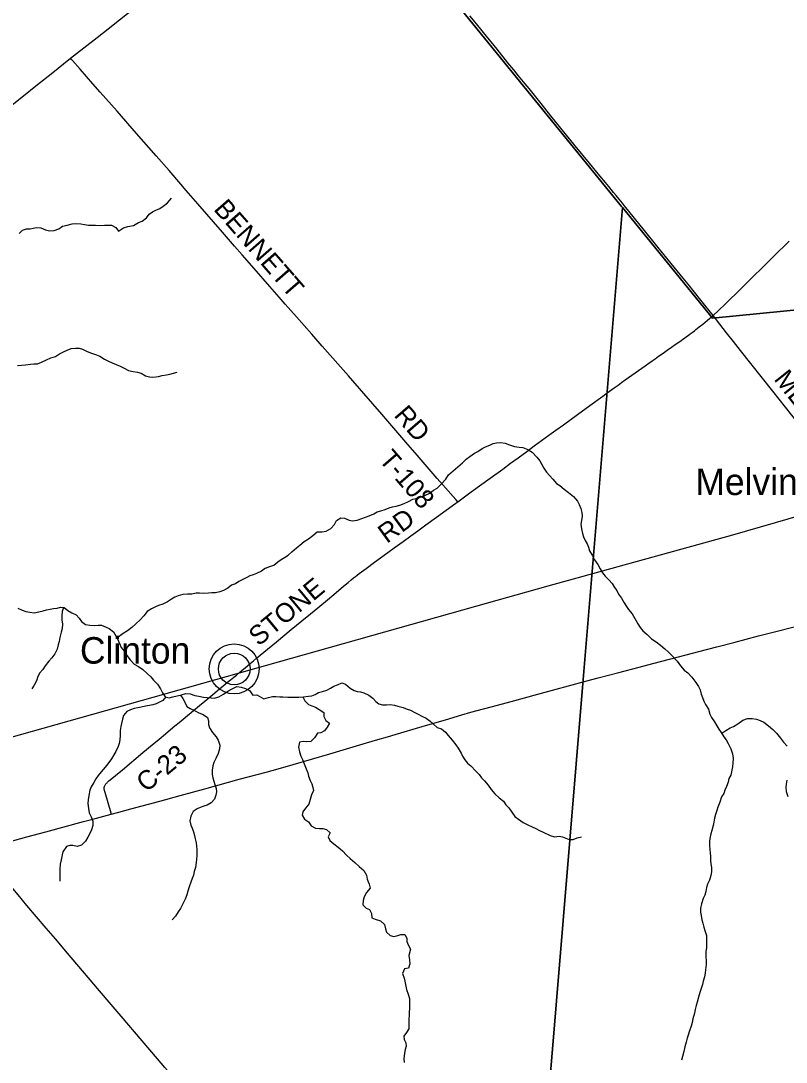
# Model space of a CAD drawing. Extents: x 1442749 to 1756758, y 235267 to 677782.
# Drawn here: x 1611789 to 1623834, y 530141 to 546534 of the extents above; entities that cross this region are included whole.
import ezdxf

# ---------------------------------------------------------------- set-up
doc = ezdxf.new("R2010")
doc.units = 0
for name, color, linetype in [('GM_X_County_Road', 7, 'Continuous'), ('GM_X_County_Road_Text', 7, 'Continuous'), ('GM_X_Major_River', 7, 'Continuous'), ('GM_X_Minor_River', 7, 'Continuous'), ('GM_X_Rail_Line', 7, 'Continuous'), ('GM_X_Township', 7, 'Continuous'), ('GM_X_Township_Road', 7, 'Continuous'), ('GM_X_Township_Road_Text', 7, 'Continuous'), ('GM_X_Unincorporated', 7, 'Continuous'), ('GM_X_Unincorporated_Location', 7, 'Continuous'), ('GM_X_Unincorporated_Text', 7, 'Continuous'), ('GM_X_US_Route', 7, 'Continuous')]:
    doc.layers.add(name, color=color, linetype=linetype)

msp = doc.modelspace()

# ---------------------------------------------------------------- linework, layer by layer
at = {"layer": 'GM_X_County_Road'}
for points in [[(1612571, 545944), (1612619, 545982), (1612991, 546273), (1613163, 546410), (1613344, 546552), (1613593, 546749), (1613910, 546999), (1613982, 547057), (1614013, 547086), (1614034, 547110), (1614082, 547170), (1614090, 547182)], [(1621256, 543663), (1621205, 543726), (1621157, 543784), (1621117, 543833), (1621079, 543879), (1621043, 543924), (1620991, 543987), (1620900, 544096), (1620740, 544292), (1620514, 544569), (1620132, 545041), (1619976, 545233), (1619788, 545467), (1619725, 545545), (1619623, 545670), (1619546, 545764), (1619456, 545875), (1619284, 546086), (1619072, 546348), (1618939, 546512), (1618857, 546612)], [(1611554, 545133), (1611806, 545334), (1612054, 545532), (1612265, 545699), (1612571, 545944)], [(1622686, 541893), (1622493, 542135), (1622290, 542389), (1622214, 542483), (1622025, 542715), (1621822, 542965), (1621603, 543235), (1621288, 543623), (1621256, 543663)], [(1622686, 541893), (1622770, 541973), (1622881, 542081), (1623120, 542315), (1623298, 542494), (1623470, 542662), (1623731, 542920), (1623785, 542973), (1623880, 543067)], [(1620998, 540662), (1621052, 540702), (1621126, 540755), (1621188, 540799), (1621244, 540839), (1621302, 540881), (1621613, 541103), (1621673, 541146), (1621724, 541182), (1621770, 541215), (1621824, 541253), (1621896, 541304), (1621960, 541349), (1622029, 541397), (1622088, 541437), (1622144, 541476), (1622179, 541500), (1622208, 541521), (1622236, 541541), (1622267, 541563), (1622293, 541582), (1622323, 541605), (1622355, 541629), (1622389, 541655), (1622414, 541676), (1622464, 541715), (1622520, 541761), (1622597, 541822), (1622686, 541893)], [(1622720, 541850), (1622686, 541893)], [(1624525, 539575), (1624463, 539652), (1624024, 540199), (1623623, 540706), (1623117, 541343), (1623003, 541487), (1622897, 541623), (1622789, 541761), (1622720, 541850)], [(1618665, 538964), (1618876, 539118), (1619176, 539336), (1619373, 539479), (1619497, 539571), (1619614, 539656), (1619750, 539755), (1619869, 539842), (1619985, 539927), (1620100, 540011), (1620211, 540091), (1620329, 540177), (1620550, 540337), (1620744, 540478), (1620951, 540628), (1620998, 540662)], [(1613213, 534046), (1613209, 534061), (1613114, 534384), (1613110, 534401), (1613107, 534414), (1613104, 534425), (1613103, 534434), (1613102, 534443), (1613101, 534450), (1613102, 534460), (1613103, 534469), (1613105, 534478), (1613107, 534485), (1613111, 534494), (1613115, 534503), (1613121, 534512), (1613127, 534521), (1613133, 534528), (1613139, 534535), (1613146, 534541), (1613154, 534549), (1613164, 534558), (1613176, 534568), (1613197, 534585), (1613390, 534745), (1613711, 535014), (1613858, 535136), (1613964, 535225), (1614065, 535310), (1614144, 535376), (1614214, 535434), (1614280, 535489), (1614343, 535541), (1614410, 535597), (1614470, 535648), (1614513, 535684), (1614565, 535727), (1614608, 535763), (1614652, 535799), (1614812, 535931), (1614917, 536018), (1614974, 536065), (1615043, 536122), (1615091, 536162), (1615141, 536202), (1615183, 536236), (1615230, 536275), (1615275, 536312), (1615318, 536348), (1615399, 536417), (1615449, 536458), (1615500, 536500), (1615614, 536594), (1615811, 536757), (1616046, 536951), (1616211, 537087), (1616348, 537201), (1616461, 537295), (1616614, 537421), (1616715, 537506), (1616831, 537601), (1616895, 537654), (1616943, 537694), (1616990, 537733), (1617026, 537764), (1617056, 537788), (1617082, 537809), (1617115, 537834), (1617150, 537860), (1617185, 537886), (1617224, 537914), (1617357, 538010), (1617565, 538163), (1617667, 538237), (1617808, 538339), (1617927, 538426), (1618036, 538506), (1618164, 538600), (1618329, 538720), (1618633, 538940), (1618665, 538964)], [(1616062, 527722), (1615880, 527924), (1615778, 528043), (1615654, 528187), (1615414, 528470), (1615095, 528841), (1614595, 529431), (1614445, 529605), (1614213, 529877), (1614058, 530056), (1613941, 530193), (1613701, 530475), (1613366, 530867), (1613181, 531084), (1612938, 531369), (1612522, 531859), (1612333, 532081), (1612189, 532251), (1611886, 532610), (1611745, 532778), (1611531, 533031), (1611414, 533169), (1611334, 533264), (1611146, 533486)]]:
    msp.add_lwpolyline(points, dxfattribs=at)
at = {"layer": 'GM_X_Major_River'}
msp.add_lwpolyline([(1611741, 537288), (1611808, 537256), (1611867, 537237), (1611933, 537223), (1611997, 537214), (1612070, 537232), (1612140, 537245), (1612192, 537262), (1612251, 537275), (1612305, 537282), (1612363, 537286), (1612416, 537303), (1612472, 537300), (1612531, 537253), (1612590, 537217), (1612658, 537182), (1612705, 537131), (1612746, 537080), (1612807, 537032), (1612875, 537019), (1612947, 537017), (1613007, 537022), (1613061, 537021), (1613130, 536987), (1613182, 536966), (1613247, 536915), (1613315, 536793)], dxfattribs=at)
at = {"layer": 'GM_X_Minor_River'}
for points in [[(1611765, 543188), (1611815, 543240), (1611878, 543261), (1611934, 543261), (1611984, 543270), (1612036, 543280), (1612106, 543275), (1612178, 543246), (1612238, 543229), (1612314, 543234), (1612385, 543262), (1612447, 543301), (1612516, 543320), (1612596, 543337), (1612654, 543345), (1612734, 543338), (1612790, 543327), (1612854, 543318), (1612913, 543318), (1612965, 543315), (1613039, 543314), (1613107, 543315), (1613159, 543317), (1613217, 543316), (1613283, 543279), (1613326, 543223), (1613407, 543276), (1613472, 543299), (1613564, 543310), (1613641, 543361), (1613699, 543381), (1613766, 543432), (1613807, 543492), (1613859, 543529), (1613916, 543555), (1613976, 543582), (1614029, 543618), (1614099, 543671), (1614158, 543741)], [(1611738, 541109), (1611798, 541114), (1611864, 541117), (1611941, 541127), (1611995, 541134), (1612053, 541137), (1612117, 541161), (1612192, 541200), (1612264, 541227), (1612335, 541252), (1612397, 541292), (1612462, 541325), (1612518, 541349), (1612579, 541378), (1612651, 541381), (1612707, 541381), (1612759, 541368), (1612831, 541331), (1612903, 541302), (1612978, 541275), (1613030, 541257), (1613108, 541206), (1613170, 541175), (1613226, 541150)], [(1613226, 541150), (1613291, 541125), (1613355, 541100), (1613413, 541068), (1613483, 541029), (1613555, 541012), (1613623, 541005), (1613683, 540988), (1613752, 540947), (1613812, 540931), (1613868, 540924), (1613955, 540933), (1614013, 540950), (1614081, 540964), (1614135, 540971), (1614194, 540990), (1614248, 541006)], [(1615641, 537919), (1615706, 537942), (1615771, 537963), (1615834, 538017), (1615884, 538054), (1615941, 538088), (1615994, 538125), (1616055, 538177), (1616126, 538238), (1616180, 538282), (1616249, 538337), (1616316, 538382), (1616383, 538434), (1616454, 538491), (1616529, 538492), (1616597, 538500), (1616666, 538543), (1616727, 538604), (1616758, 538670), (1616826, 538712), (1616883, 538705), (1616957, 538676), (1617011, 538663), (1617085, 538673), (1617154, 538702), (1617214, 538723), (1617271, 538741), (1617343, 538772), (1617396, 538805), (1617453, 538823), (1617523, 538840), (1617586, 538869), (1617636, 538885), (1617696, 538894), (1617753, 538908), (1617822, 538935), (1617890, 538966), (1617957, 539002), (1618031, 539019), (1618098, 539046), (1618148, 539062), (1618225, 539101), (1618284, 539146), (1618339, 539178), (1618402, 539239), (1618477, 539317), (1618520, 539386), (1618595, 539452), (1618666, 539515), (1618739, 539577), (1618800, 539632), (1618853, 539674), (1618930, 539727), (1618980, 539754), (1619051, 539802), (1619102, 539827), (1619169, 539855), (1619223, 539880), (1619277, 539891), (1619346, 539897), (1619410, 539886), (1619478, 539857), (1619558, 539832), (1619632, 539823), (1619688, 539815), (1619766, 539784), (1619836, 539745), (1619909, 539666), (1619955, 539609), (1619988, 539548), (1620020, 539490), (1620061, 539431), (1620113, 539373), (1620160, 539318), (1620222, 539251), (1620274, 539218), (1620339, 539161), (1620407, 539111), (1620489, 539045), (1620548, 538975), (1620575, 538918), (1620603, 538856), (1620618, 538793), (1620623, 538737), (1620615, 538669), (1620602, 538609), (1620613, 538535), (1620630, 538462), (1620644, 538410), (1620673, 538355), (1620703, 538301), (1620722, 538247), (1620739, 538190), (1620779, 538122), (1620816, 538051), (1620869, 537974), (1620909, 537907), (1620946, 537845), (1620984, 537794), (1621043, 537735), (1621093, 537679)], [(1615641, 537919), (1615576, 537869), (1615500, 537832), (1615445, 537813), (1615395, 537795), (1615344, 537772), (1615273, 537734), (1615221, 537709), (1615166, 537671), (1615106, 537648), (1615049, 537604), (1614978, 537565), (1614922, 537548), (1614853, 537532), (1614797, 537529), (1614743, 537526), (1614670, 537520), (1614602, 537523), (1614550, 537522), (1614479, 537511), (1614411, 537507), (1614341, 537504), (1614264, 537485), (1614213, 537461), (1614161, 537428), (1614098, 537388), (1614023, 537353), (1613955, 537330), (1613900, 537306), (1613844, 537279), (1613779, 537236), (1613726, 537170), (1613665, 537106), (1613600, 537041), (1613535, 536982), (1613470, 536930), (1613399, 536891), (1613302, 536815)], [(1621093, 537679), (1621132, 537616), (1621168, 537564), (1621195, 537511), (1621241, 537444), (1621282, 537374), (1621319, 537315), (1621351, 537265), (1621408, 537198), (1621450, 537123), (1621499, 537042), (1621538, 536982), (1621578, 536931), (1621648, 536876), (1621717, 536805), (1621787, 536758), (1621854, 536707), (1621922, 536648), (1621984, 536596), (1622047, 536531), (1622119, 536454), (1622170, 536379), (1622231, 536314), (1622287, 536269), (1622347, 536204), (1622414, 536119), (1622455, 536055), (1622479, 536004), (1622498, 535934), (1622515, 535880), (1622537, 535825), (1622564, 535773), (1622610, 535698), (1622635, 535618), (1622658, 535567), (1622704, 535500), (1622743, 535438), (1622775, 535383), (1622812, 535333), (1622853, 535264), (1622891, 535213), (1622922, 535157), (1622962, 535074), (1622987, 534996), (1623000, 534921), (1622993, 534855), (1622990, 534791), (1622980, 534739), (1622961, 534659), (1622934, 534607), (1622921, 534551), (1622896, 534483), (1622869, 534423), (1622851, 534371), (1622818, 534316), (1622791, 534236), (1622758, 534154), (1622741, 534102), (1622722, 534038), (1622705, 533980), (1622697, 533920), (1622684, 533868), (1622663, 533790), (1622650, 533738), (1622633, 533664), (1622627, 533614), (1622628, 533546), (1622631, 533493), (1622636, 533433), (1622642, 533383), (1622645, 533313), (1622650, 533261), (1622660, 533206), (1622661, 533138), (1622648, 533080), (1622625, 533008), (1622598, 532946), (1622582, 532890), (1622571, 532828), (1622552, 532772), (1622527, 532720), (1622500, 532636), (1622485, 532560), (1622485, 532504), (1622494, 532448), (1622505, 532384), (1622523, 532329), (1622538, 532267), (1622553, 532213), (1622579, 532134), (1622578, 532078), (1622581, 532018), (1622580, 531943), (1622568, 531881), (1622569, 531809), (1622576, 531727), (1622575, 531677), (1622566, 531595), (1622561, 531544), (1622549, 531484), (1622528, 531418)], [(1612459, 537301), (1612441, 537236), (1612433, 537170), (1612436, 537104), (1612443, 537035), (1612438, 536967), (1612422, 536913), (1612402, 536827), (1612390, 536763), (1612379, 536713), (1612362, 536645), (1612325, 536570), (1612276, 536506), (1612232, 536454), (1612171, 536379), (1612134, 536323), (1612089, 536271), (1612058, 536210), (1612034, 536142), (1612001, 536078), (1611960, 536016)], [(1613315, 536793), (1613367, 536670), (1613422, 536605), (1613459, 536542), (1613509, 536474), (1613574, 536409), (1613640, 536368), (1613707, 536325), (1613775, 536262), (1613836, 536205), (1613878, 536153), (1613941, 536092), (1613986, 536021), (1614018, 535954), (1614063, 535892), (1614123, 535877), (1614179, 535890), (1614251, 535906), (1614320, 535925), (1614384, 535946), (1614452, 535939), (1614526, 535913), (1614590, 535902), (1614666, 535887), (1614724, 535880), (1614784, 535875), (1614836, 535873), (1614907, 535894), (1614977, 535935), (1615048, 535981), (1615117, 536020), (1615191, 536053), (1615255, 536045), (1615325, 536022), (1615387, 535993), (1615438, 535920), (1615506, 535923), (1615613, 535863)], [(1615613, 535863), (1615685, 535882), (1615752, 535898), (1615802, 535897), (1615864, 535890), (1615914, 535890), (1615993, 535887), (1616059, 535888), (1616166, 535887), (1616240, 535890), (1616316, 535903), (1616369, 535909), (1616421, 535928), (1616472, 535962), (1616536, 535977), (1616607, 535998), (1616665, 536030), (1616716, 536061), (1616775, 536083), (1616843, 536114), (1616897, 536093), (1616973, 536030), (1617033, 535993), (1617085, 535975), (1617137, 535970), (1617187, 535956), (1617267, 535917), (1617330, 535872), (1617374, 535821), (1617426, 535782), (1617482, 535764), (1617544, 535767), (1617600, 535770), (1617669, 535760), (1617723, 535745), (1617805, 535722), (1617869, 535699), (1617923, 535681), (1617989, 535648), (1618045, 535617), (1618102, 535590), (1618166, 535556), (1618232, 535511), (1618284, 535460), (1618343, 535409), (1618411, 535388), (1618471, 535335), (1618513, 535285), (1618578, 535210), (1618637, 535135), (1618671, 535084), (1618718, 535008), (1618742, 534957), (1618777, 534899), (1618819, 534848), (1618870, 534807), (1618950, 534724), (1619003, 534670), (1619041, 534619), (1619084, 534568), (1619146, 534503), (1619189, 534435), (1619251, 534366), (1619316, 534301), (1619388, 534250), (1619421, 534193), (1619469, 534143), (1619514, 534078), (1619566, 534011), (1619624, 533969), (1619695, 533916), (1619769, 533875), (1619835, 533848), (1619895, 533819), (1619953, 533790), (1620011, 533764), (1620119, 533710), (1620187, 533691), (1620259, 533697), (1620313, 533686), (1620365, 533665), (1620417, 533647), (1620480, 533644), (1620544, 533671), (1620611, 533689)], [(1614304, 535920), (1614337, 535865), (1614371, 535810), (1614404, 535739), (1614456, 535711), (1614535, 535672), (1614589, 535643), (1614659, 535614), (1614726, 535565), (1614742, 535513), (1614745, 535459), (1614759, 535404), (1614808, 535332), (1614863, 535263), (1614893, 535208), (1614922, 535134), (1614917, 535074), (1614896, 535002), (1614865, 534934), (1614826, 534860), (1614810, 534806), (1614799, 534740), (1614802, 534670), (1614809, 534618), (1614825, 534563), (1614842, 534513), (1614861, 534451), (1614869, 534396), (1614860, 534344), (1614837, 534280), (1614787, 534223), (1614722, 534185), (1614668, 534170), (1614613, 534149), (1614563, 534127), (1614502, 534088), (1614465, 534016), (1614451, 533942), (1614466, 533873), (1614485, 533823), (1614507, 533769), (1614522, 533708), (1614535, 533658), (1614547, 533594), (1614554, 533542), (1614557, 533489), (1614561, 533439), (1614560, 533387), (1614556, 533335), (1614549, 533283), (1614536, 533207), (1614519, 533141), (1614507, 533087), (1614486, 533033), (1614465, 532977), (1614436, 532901), (1614417, 532831), (1614401, 532773), (1614376, 532705), (1614341, 532633), (1614300, 532562), (1614263, 532510), (1614224, 532440), (1614173, 532381)], [(1614071, 535890), (1614026, 535836), (1613974, 535809), (1613919, 535781), (1613865, 535768), (1613813, 535756), (1613750, 535743), (1613684, 535730), (1613628, 535720), (1613572, 535707), (1613513, 535689), (1613459, 535662), (1613406, 535596), (1613389, 535540), (1613372, 535474), (1613362, 535424), (1613353, 535360), (1613354, 535282), (1613349, 535214), (1613337, 535160), (1613320, 535108), (1613287, 535034), (1613254, 534980), (1613216, 534917), (1613158, 534837), (1613116, 534783), (1613053, 534710), (1613008, 534656), (1612969, 534599), (1612936, 534543), (1612896, 534475), (1612877, 534423), (1612862, 534337), (1612851, 534269), (1612846, 534213), (1612855, 534135), (1612867, 534066), (1612894, 534002), (1612921, 533935), (1612924, 533869), (1612904, 533797), (1612877, 533739), (1612844, 533685), (1612805, 533618), (1612742, 533556), (1612674, 533537), (1612610, 533554), (1612560, 533554), (1612510, 533535), (1612449, 533455), (1612442, 533403), (1612423, 533325), (1612406, 533257), (1612405, 533183), (1612403, 533123), (1612401, 532991)], [(1616227, 535890), (1616257, 535832), (1616319, 535773), (1616371, 535752), (1616425, 535730), (1616485, 535693), (1616556, 535646), (1616558, 535584), (1616591, 535521), (1616649, 535480), (1616608, 535417), (1616569, 535355), (1616512, 535327), (1616458, 535322), (1616413, 535248), (1616354, 535187), (1616286, 535186), (1616231, 535190), (1616173, 535177), (1616158, 535099), (1616175, 535026), (1616198, 534956), (1616222, 534905), (1616249, 534839), (1616282, 534760), (1616306, 534696), (1616317, 534644), (1616345, 534575), (1616368, 534525), (1616385, 534466), (1616393, 534416), (1616366, 534352), (1616343, 534274), (1616320, 534204), (1616271, 534139), (1616228, 534083), (1616219, 534029), (1616255, 533968), (1616317, 533926), (1616358, 533861), (1616428, 533826), (1616488, 533819), (1616544, 533819), (1616598, 533804), (1616658, 533749), (1616625, 533687), (1616651, 533633), (1616714, 533576), (1616782, 533525), (1616849, 533468), (1616913, 533399), (1616973, 533345), (1617046, 533282), (1617112, 533223), (1617185, 533156), (1617227, 533085), (1617240, 533023), (1617269, 532946), (1617288, 532882), (1617231, 532814), (1617194, 532742), (1617177, 532684), (1617173, 532618), (1617222, 532565), (1617274, 532543), (1617308, 532484), (1617315, 532414), (1617367, 532393), (1617449, 532366), (1617510, 532311), (1617528, 532239), (1617545, 532189), (1617603, 532136), (1617659, 532119), (1617721, 532133), (1617772, 532152), (1617834, 532149), (1617865, 532095), (1617865, 532043), (1617886, 531990), (1617920, 531922), (1617898, 531822), (1617905, 531751), (1617911, 531687), (1617888, 531623), (1617827, 531608), (1617794, 531536), (1617822, 531465), (1617833, 531415), (1617846, 531337), (1617858, 531287), (1617887, 531210), (1617906, 531144), (1617904, 530983), (1617902, 530933), (1617901, 530875), (1617898, 530821), (1617897, 530714), (1617898, 530664), (1617860, 530608), (1617819, 530553)], [(1622821, 535319), (1622887, 535362), (1622952, 535405), (1623006, 535425), (1623075, 535470), (1623150, 535523), (1623228, 535549), (1623299, 535552), (1623365, 535541), (1623427, 535522), (1623483, 535492), (1623557, 535437), (1623626, 535380), (1623682, 535321), (1623747, 535244), (1623793, 535181), (1623848, 535114)], [(1623844, 534581), (1623833, 534517), (1623828, 534465), (1623833, 534403), (1623861, 534326)], [(1622528, 531418), (1622515, 531362), (1622496, 531300), (1622477, 531236), (1622454, 531163), (1622433, 531087), (1622417, 531035), (1622402, 530969), (1622389, 530914), (1622366, 530822), (1622353, 530766), (1622338, 530708), (1622310, 530637), (1622289, 530567), (1622278, 530517), (1622261, 530457), (1622240, 530385), (1622223, 530309), (1622202, 530229), (1622187, 530175)], [(1617819, 530553), (1617822, 530499), (1617848, 530446), (1617853, 530394), (1617838, 530340), (1617826, 530282), (1617816, 530194), (1617822, 530135)]]:
    msp.add_lwpolyline(points, dxfattribs=at)
at = {"layer": 'GM_X_Rail_Line'}
msp.add_lwpolyline([(1602593, 532708), (1605889, 533638), (1608879, 534480), (1615229, 536269), (1618948, 537318), (1620090, 537639), (1622993, 538441), (1624974, 539014)], dxfattribs=at)
at = {"layer": 'GM_X_Township'}
for points in [[(1644898, 555254), (1644396, 554944), (1643852, 554569), (1643512, 554247), (1640924, 550208), (1640433, 549458), (1639325, 548457), (1635524, 544621), (1633902, 542962), (1622672, 541854), (1621259, 543594), (1621243, 543613), (1617735, 547931), (1616706, 549187), (1616628, 549233), (1615854, 549688), (1611427, 552129), (1613178, 554457), (1615321, 557320)], [(1653261, 533457), (1649470, 532440), (1648625, 532214), (1643929, 530963), (1641622, 530343), (1638146, 529408), (1628661, 526876), (1619669, 524461), (1619911, 527377), (1620636, 536103), (1621013, 540634), (1621259, 543594), (1622672, 541854), (1633902, 542962), (1635524, 544621), (1639325, 548457), (1640433, 549458), (1640924, 550208), (1643512, 554247), (1643852, 554569), (1644396, 554944), (1644898, 555254)], [(1601615, 552912), (1606228, 552538), (1611427, 552129), (1615854, 549688), (1616628, 549233), (1616706, 549187), (1617735, 547931), (1621243, 543613), (1621259, 543594), (1621013, 540634), (1620636, 536103), (1619911, 527377)]]:
    msp.add_lwpolyline(points, dxfattribs=at)
at = {"layer": 'GM_X_Township_Road'}
msp.add_lwpolyline([(1618665, 538964), (1618634, 538999), (1618471, 539184), (1618344, 539330), (1618186, 539514), (1618027, 539697), (1617850, 539904), (1617661, 540122), (1617470, 540343), (1617187, 540667), (1616945, 540944), (1616531, 541414), (1616367, 541602), (1616126, 541875), (1615950, 542074), (1615855, 542183), (1615707, 542353), (1615460, 542635), (1615272, 542849), (1615151, 542988), (1614963, 543206), (1614575, 543652), (1614392, 543862), (1614306, 543962), (1614123, 544176), (1613920, 544408), (1613611, 544761), (1613305, 545112), (1613039, 545412), (1612924, 545542), (1612721, 545774), (1612601, 545909), (1612589, 545924), (1612571, 545944)], dxfattribs=at)
at = {"layer": 'GM_X_Unincorporated'}
for radius in [393, 249]:
    msp.add_circle((1615147, 536332), radius, dxfattribs=at)
at = {"layer": 'GM_X_Unincorporated_Location'}
msp.add_line((1615147, 536332), (1615147, 536332), dxfattribs=at)
at = {"layer": 'GM_X_US_Route'}
for points in [[(1617599, 535275), (1617630, 535284), (1618158, 535441), (1618475, 535533), (1618731, 535610), (1618873, 535650), (1619291, 535763), (1619507, 535820), (1619925, 535934), (1620042, 535967), (1620580, 536112), (1620776, 536165), (1620875, 536191), (1621201, 536278), (1621519, 536361), (1621734, 536418), (1622261, 536556), (1622458, 536607), (1622741, 536679), (1623008, 536749), (1623398, 536852), (1623627, 536910), (1623980, 537000)], [(1611114, 533477), (1611146, 533486), (1611884, 533686), (1612185, 533768), (1612774, 533928), (1612923, 533968), (1613097, 534014), (1613213, 534046), (1613334, 534079), (1613522, 534128), (1613978, 534252), (1614297, 534339), (1614684, 534443), (1615227, 534594), (1615652, 534709), (1615839, 534760), (1616075, 534827), (1616654, 534997), (1617126, 535136), (1617372, 535209), (1617599, 535275)]]:
    msp.add_lwpolyline(points, dxfattribs=at)

# ---------------------------------------------------------------- texts
at = {"layer": 'GM_X_County_Road_Text'}
for s, rotation, p in [('MELVIN', 308.4956, (1623630, 540891)), ('RD', 35.9928, (1617549, 538298)), ('STONE', 39.6428, (1615532, 536679)), ('C-23', 39.677, (1613763, 534378))]:
    msp.add_text(s, height=300, rotation=rotation, dxfattribs=at).set_placement(p)
at = {"layer": 'GM_X_Township_Road_Text'}
for s, rotation, p in [('BENNETT', 311.0719, (1614811, 543563)), ('RD', 310.8054, (1617649, 540319)), ('T-108', 310.8754, (1617411, 539619))]:
    msp.add_text(s, height=300, rotation=rotation, dxfattribs=at).set_placement(p)
at = {"layer": 'GM_X_Unincorporated_Text'}
for s, p in [('Melvin', (1622405, 539069)), ('Clinton', (1612720, 536415))]:
    msp.add_text(s, height=417, rotation=0, dxfattribs=at).set_placement(p)

doc.saveas('drawing.dxf')
